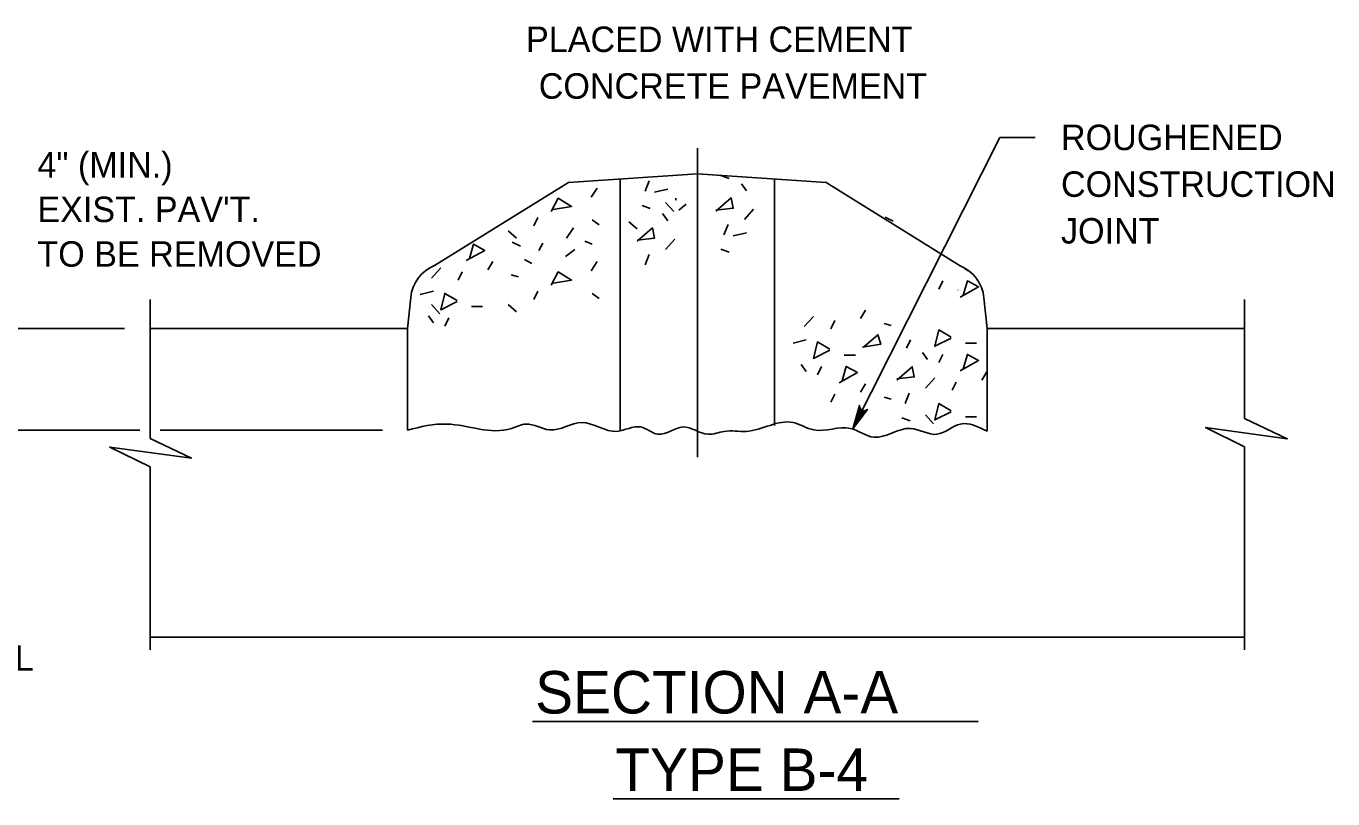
# Model space of a CAD drawing. Extents: x -7.6 to -0.4, y 98.1 to 108.3.
# Drawn here: x -3.651 to -0.576, y 104.417 to 106.236 of the extents above; entities that cross this region are included whole.
import ezdxf

# ---------------------------------------------------------------- set-up
doc = ezdxf.new("R2010")
doc.units = 0
for name, color, linetype in [('DETL-DIMS', 7, 'Continuous'), ('DETL-LINE', 7, 'Continuous'), ('DETL-NOTE', 7, 'Continuous'), ('DETL-PATT', 7, 'Continuous'), ('DETL-TITL', 7, 'Continuous')]:
    doc.layers.add(name, color=color, linetype=linetype)

msp = doc.modelspace()

# ---------------------------------------------------------------- linework, layer by layer
at = {"layer": 'DETL-DIMS'}
for p, q in [((-1.3591, 105.9746), (-1.7057, 105.2883)), ((-1.276, 105.9746), (-1.3591, 105.9746)), ((-2.0712, 105.2213), (-2.0712, 105.9491)), ((-3.4196, 105.5249), (-3.7881, 105.5249)), ((-3.3833, 105.2855), (-3.7881, 105.2855)), ((-2.8122, 105.2855), (-3.3357, 105.2855))]:
    msp.add_line(p, q, dxfattribs=at)
msp.add_lwpolyline([(-1.7057, 105.2883), (-1.6897, 105.3435), (-1.6889, 105.3382), (-1.6866, 105.3345), (-1.6835, 105.3322), (-1.6798, 105.3311), (-1.6754, 105.3314), (-1.6708, 105.3339), (-1.7057, 105.2883), (-1.6754, 105.3314), (-1.6798, 105.3311), (-1.7057, 105.2883), (-1.6835, 105.3322), (-1.6866, 105.3345), (-1.7057, 105.2883), (-1.6889, 105.3382)], dxfattribs=at)
at = {"layer": 'DETL-LINE'}
for p, q in [((-2.3743, 105.8683), (-2.0712, 105.8885)), ((-1.7682, 105.8683), (-2.0712, 105.8885)), ((-2.3743, 105.8683), (-2.6897, 105.6728)), ((-2.2531, 105.2825), (-2.2531, 105.8764)), ((-1.8894, 105.2962), (-1.8894, 105.8764)), ((-1.7682, 105.8683), (-1.4526, 105.672)), ((-3.359, 105.5932), (-3.359, 105.2656)), ((-2.753, 105.5249), (-2.7457, 105.5977)), ((-1.3895, 105.5249), (-1.3967, 105.5969)), ((-0.7835, 105.5932), (-0.7835, 105.3128)), ((-3.359, 105.5249), (-2.753, 105.5249)), ((-2.753, 105.5249), (-2.753, 105.2855)), ((-1.3895, 105.5249), (-0.7835, 105.5249)), ((-1.3895, 105.5249), (-1.3895, 105.2825)), ((-0.7835, 105.2462), (-0.7835, 104.7677)), ((-3.359, 105.199), (-3.359, 104.7677)), ((-3.359, 104.7976), (-0.7835, 104.7976))]:
    msp.add_line(p, q, dxfattribs=at)
for points in [[(-0.7835, 105.2462), (-0.8753, 105.2912), (-0.6831, 105.265), (-0.7835, 105.3128)], [(-3.359, 105.199), (-3.4542, 105.2455), (-3.2619, 105.2194), (-3.359, 105.2656)]]:
    msp.add_lwpolyline(points, dxfattribs=at)
for centre, start, end in [((-2.6552, 105.5886), 112.2917, 174.2894), ((-1.4872, 105.5879), 5.7107, 67.6341)]:
    msp.add_arc(centre, 0.0909, start, end, dxfattribs=at)
msp.add_spline([(-2.753, 105.2855), (-2.6608, 105.2997), (-2.5088, 105.2893), (-2.4743, 105.2997), (-2.419, 105.2858), (-2.3431, 105.3031), (-2.2602, 105.2824), (-2.2049, 105.2927), (-2.1635, 105.2755), (-2.1048, 105.2927), (-2.046, 105.2755), (-2.008, 105.2824), (-1.9563, 105.2824), (-1.8457, 105.3031), (-1.7974, 105.2858), (-1.711, 105.2893), (-1.6558, 105.2686), (-1.5694, 105.2893), (-1.5073, 105.2755), (-1.452, 105.2997), (-1.3895, 105.2825)], degree=3, dxfattribs=at)
at = {"layer": 'DETL-PATT'}
for p, q in [((-2.0157, 105.8847), (-1.9964, 105.8775)), ((-2.3069, 105.8553), (-2.3213, 105.8336)), ((-2.1843, 105.872), (-2.194, 105.8479)), ((-2.141, 105.8528), (-2.1723, 105.8456)), ((-1.9676, 105.8655), (-1.9555, 105.8486)), ((-2.1458, 105.8215), (-2.1266, 105.7998)), ((-2.1144, 105.8029), (-2.0975, 105.8173)), ((-2.2012, 105.8143), (-2.1819, 105.807)), ((-2.153, 105.795), (-2.141, 105.7782)), ((-1.9387, 105.8053), (-1.9604, 105.7812)), ((-1.6295, 105.7865), (-1.6102, 105.7769)), ((-2.4561, 105.7662), (-2.4465, 105.7855)), ((-2.3623, 105.7614), (-2.3791, 105.7373)), ((-2.3189, 105.7807), (-2.3021, 105.7686)), ((-2.2325, 105.7757), (-2.2132, 105.7589)), ((-1.9989, 105.7692), (-2.0085, 105.7451)), ((-2.5163, 105.7542), (-2.497, 105.7373)), ((-2.5067, 105.7277), (-2.4874, 105.7181)), ((-2.4441, 105.7084), (-2.4345, 105.7253)), ((-2.3358, 105.7301), (-2.3189, 105.7229)), ((-2.1242, 105.7348), (-2.1458, 105.7108)), ((-1.9555, 105.75), (-1.9868, 105.7427)), ((-2.3598, 105.7108), (-2.3815, 105.694)), ((-2.1843, 105.6987), (-2.194, 105.6747)), ((-2.0157, 105.7114), (-1.9964, 105.7042)), ((-2.6752, 105.6675), (-2.6968, 105.6434)), ((-2.5644, 105.6627), (-2.5524, 105.682)), ((-2.4778, 105.6868), (-2.4609, 105.6772)), ((-2.3069, 105.682), (-2.3213, 105.6603)), ((-1.4418, 105.6661), (-1.4335, 105.6603)), ((-2.6246, 105.6579), (-2.6342, 105.6386)), ((-2.5091, 105.6507), (-2.4922, 105.6459)), ((-1.4934, 105.6367), (-1.503, 105.6175)), ((-2.692, 105.6122), (-2.7233, 105.6049)), ((-2.4561, 105.5929), (-2.4465, 105.6122)), ((-2.3189, 105.6073), (-2.3021, 105.5953)), ((-1.4586, 105.6156), (-1.4571, 105.615)), ((-2.6968, 105.5809), (-2.6775, 105.5592)), ((-2.6029, 105.5761), (-2.5765, 105.5761)), ((-2.5163, 105.5809), (-2.497, 105.564)), ((-2.704, 105.5544), (-2.692, 105.5376)), ((-2.6559, 105.5496), (-2.6655, 105.5303)), ((-1.798, 105.553), (-1.8196, 105.5289)), ((-1.7474, 105.5434), (-1.757, 105.5241)), ((-1.6873, 105.5482), (-1.6752, 105.5675)), ((-1.6319, 105.5362), (-1.615, 105.5314)), ((-1.8148, 105.4977), (-1.8461, 105.4904)), ((-1.5789, 105.4784), (-1.5693, 105.4977)), ((-1.4405, 105.4899), (-1.414, 105.4899)), ((-1.7258, 105.4616), (-1.6993, 105.4616)), ((-1.5415, 105.4682), (-1.5295, 105.4514)), ((-1.4934, 105.4634), (-1.503, 105.4442)), ((-1.8269, 105.4399), (-1.8148, 105.4231)), ((-1.7787, 105.4351), (-1.7883, 105.4158)), ((-1.4019, 105.4033), (-1.3899, 105.4225)), ((-1.6873, 105.3749), (-1.6752, 105.3942)), ((-1.5127, 105.4081), (-1.5343, 105.384)), ((-1.4621, 105.3984), (-1.4718, 105.3792)), ((-1.7474, 105.3701), (-1.757, 105.3508)), ((-1.6319, 105.3629), (-1.615, 105.3581)), ((-1.5728, 105.372), (-1.5825, 105.3479)), ((-1.5897, 105.3142), (-1.5704, 105.307)), ((-1.5343, 105.3214), (-1.5151, 105.2998)), ((-1.4405, 105.3166), (-1.414, 105.3166))]:
    msp.add_line(p, q, dxfattribs=at)
for points in [[(-2.4152, 105.7999), (-2.3984, 105.8312), (-2.3671, 105.8119), (-2.4104, 105.8047)], [(-2.1221, 105.8268), (-2.1216, 105.827), (-2.1221, 105.8315)], [(-2.0277, 105.8029), (-1.9868, 105.8077), (-1.9916, 105.8318), (-2.0277, 105.8005)], [(-2.2132, 105.7324), (-2.1723, 105.7372), (-2.1771, 105.7613), (-2.2132, 105.73)], [(-2.615, 105.6844), (-2.5717, 105.7084), (-2.5981, 105.7229), (-2.6078, 105.6892)], [(-2.4152, 105.6266), (-2.3984, 105.6579), (-2.3671, 105.6386), (-2.4104, 105.6314)], [(-1.4525, 105.5982), (-1.4092, 105.6223), (-1.4357, 105.6367), (-1.4453, 105.603)], [(-2.6366, 105.5881), (-2.6752, 105.5688), (-2.6655, 105.6073), (-2.6366, 105.5905)], [(-1.6824, 105.4808), (-1.6391, 105.488), (-1.6463, 105.5097), (-1.68, 105.4808)], [(-1.4742, 105.5019), (-1.5127, 105.4827), (-1.503, 105.5212), (-1.4742, 105.5043)], [(-1.7595, 105.4736), (-1.798, 105.4543), (-1.7883, 105.4928), (-1.7595, 105.476)], [(-1.4525, 105.4249), (-1.4092, 105.449), (-1.4357, 105.4634), (-1.4453, 105.4297)], [(-1.7378, 105.3966), (-1.6945, 105.4206), (-1.7209, 105.4351), (-1.7306, 105.4014)], [(-1.6017, 105.4057), (-1.5608, 105.4105), (-1.5656, 105.4346), (-1.6017, 105.4033)], [(-1.4742, 105.3286), (-1.5127, 105.3094), (-1.503, 105.3479), (-1.4742, 105.3311)]]:
    msp.add_lwpolyline(points, dxfattribs=at)
at = {"layer": 'DETL-TITL'}
for p, q in [((-2.4593, 104.5996), (-1.4102, 104.5996)), ((-2.2697, 104.4172), (-1.5965, 104.4172))]:
    msp.add_line(p, q, dxfattribs=at)

# ---------------------------------------------------------------- texts
at = {"layer": 'DETL-NOTE'}
for s, p in [('PLACED WITH CEMENT', (-2.4744, 106.1755)), ('CONCRETE PAVEMENT', (-2.4444, 106.0655)), ('ROUGHENED', (-1.2154, 105.9445)), ('4" (MIN.)', (-3.6243, 105.88)), ('CONSTRUCTION', (-1.2154, 105.8345)), ("EXIST. PAV'T.", (-3.6243, 105.775)), ('JOINT', (-1.2154, 105.7245)), ('TO BE REMOVED', (-3.6243, 105.67)), ('BELOW FINAL', (-4.1722, 104.719))]:
    msp.add_text(s, height=0.06, dxfattribs=at).set_placement(p)
at = {"layer": 'DETL-TITL'}
for s, p in [('SECTION A-A', (-2.4529, 104.6182)), ('TYPE B-4', (-2.2641, 104.4358))]:
    msp.add_text(s, height=0.1, dxfattribs=at).set_placement(p)

doc.saveas('drawing.dxf')
